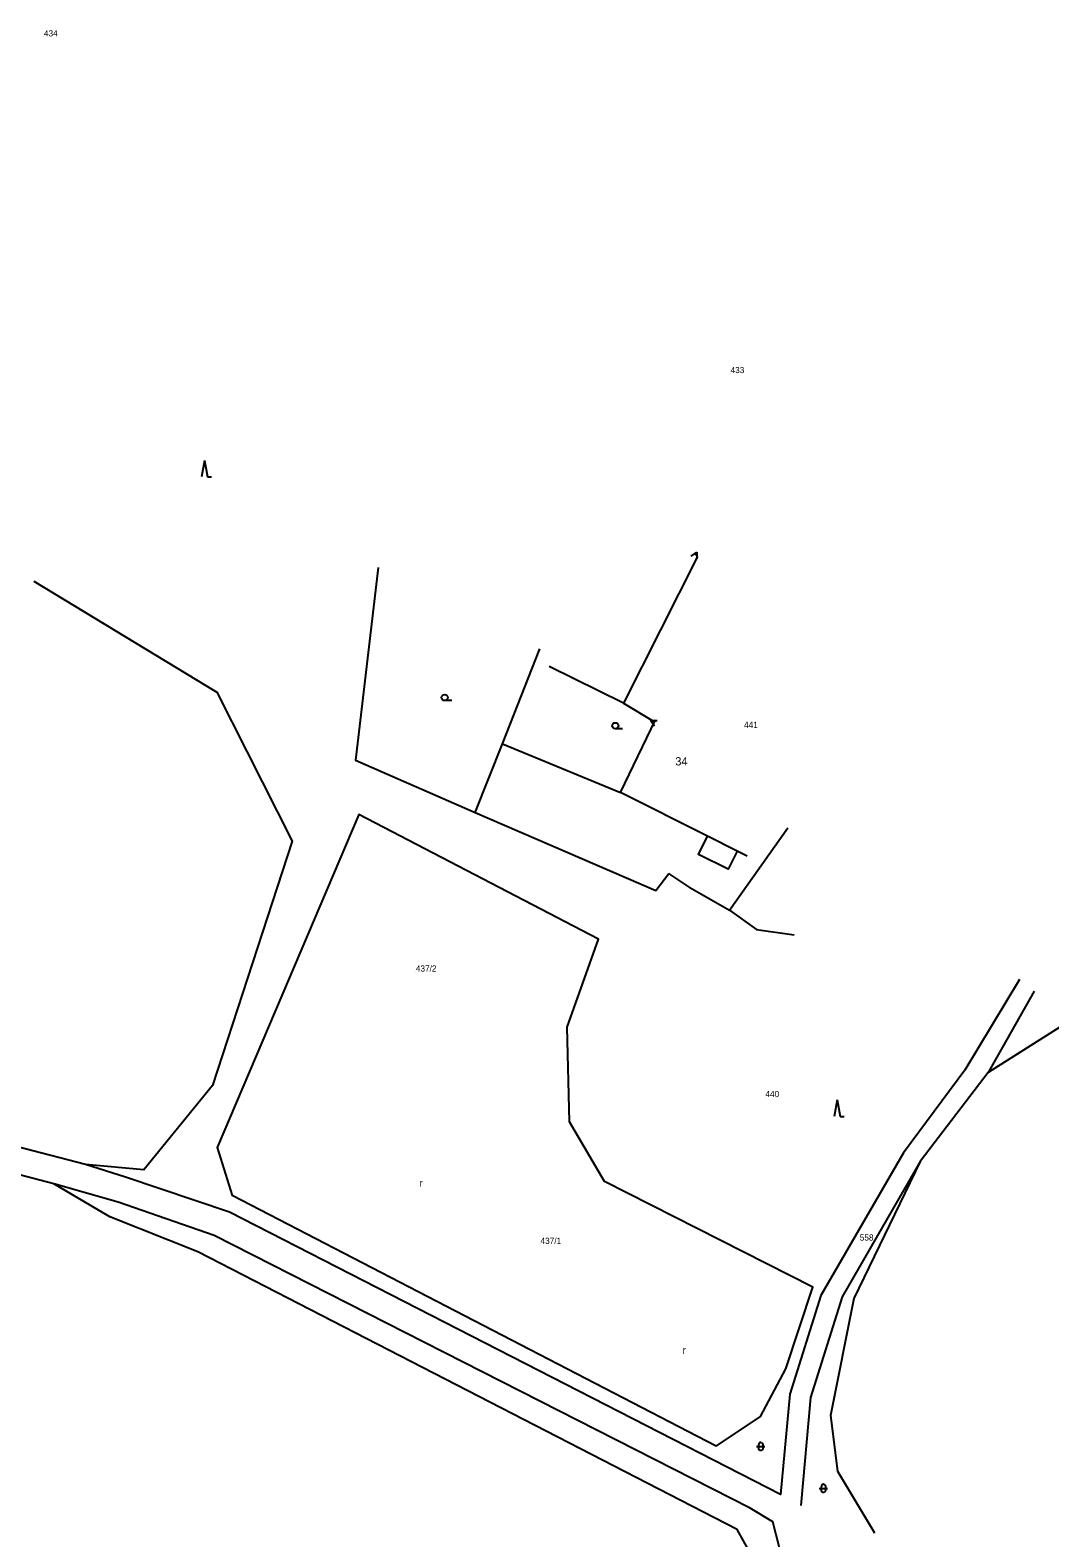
# Model space of a CAD drawing. Extents: x -836739 to -835945, y -1070775 to -1070126.
# Drawn here: x -836135.3 to -836011.5, y -1070527.3 to -1070344.2 of the extents above; entities that cross this region are included whole.
import ezdxf

# ---------------------------------------------------------------- set-up
doc = ezdxf.new("R2010")
doc.units = 0
for name, color, linetype in [('BodPole_mer', 7, 'Continuous'), ('Budovy_hranice', 7, 'Continuous'), ('Doprava_hranice', 7, 'Continuous'), ('OstPloch_hranice', 7, 'Continuous'), ('OstPloch_kody', 7, 'Continuous'), ('PovrZnIS_body', 7, 'Continuous'), ('RuianAdr_popis', 7, 'Continuous'), ('RuianPar_popis', 7, 'Continuous'), ('Stavby_hr_zed', 7, 'Continuous'), ('Stavby_linie', 7, 'Continuous')]:
    doc.layers.add(name, color=color, linetype=linetype)

msp = doc.modelspace()

# ---------------------------------------------------------------- linework, layer by layer
at = {"layer": 'BodPole_mer'}
for p, q in [((-836054.39, -1070407.61), (-836054.39, -1070407.61)), ((-836054.31, -1070408.11), (-836054.31, -1070408.11)), ((-836093.09, -1070409.47), (-836093.09, -1070409.47)), ((-836134.89, -1070411.1), (-836134.89, -1070411.1)), ((-836073.44, -1070419.35), (-836073.44, -1070419.35)), ((-836072.33, -1070421.47), (-836072.33, -1070421.47)), ((-836112.67, -1070424.6), (-836112.67, -1070424.6)), ((-836063.27, -1070425.93), (-836063.27, -1070425.93)), ((-836060, -1070428.04), (-836060, -1070428.04)), ((-836059.53, -1070428.2), (-836059.53, -1070428.2)), ((-836059.4, -1070427.97), (-836059.4, -1070427.97)), ((-836077.99, -1070430.89), (-836077.99, -1070430.89)), ((-836095.81, -1070432.85), (-836095.81, -1070432.85)), ((-836063.66, -1070436.78), (-836063.66, -1070436.78)), ((-836081.31, -1070439.23), (-836081.31, -1070439.23)), ((-836095.44, -1070439.46), (-836095.44, -1070439.46)), ((-836043.33, -1070441.08), (-836043.33, -1070441.08)), ((-836103.5, -1070442.7), (-836103.5, -1070442.7)), ((-836053.08, -1070442.11), (-836053.08, -1070442.11)), ((-836054.2, -1070444.33), (-836054.2, -1070444.33)), ((-836049.48, -1070443.92), (-836049.48, -1070443.92)), ((-836048.27, -1070444.53), (-836048.27, -1070444.53)), ((-836057.77, -1070446.61), (-836057.77, -1070446.61)), ((-836050.58, -1070446.1), (-836050.58, -1070446.1)), ((-836055.24, -1070448.33), (-836055.24, -1070448.33)), ((-836059.36, -1070448.71), (-836059.36, -1070448.71)), ((-836106.5, -1070451.88), (-836106.5, -1070451.88)), ((-836050.41, -1070451.1), (-836050.41, -1070451.1)), ((-836047.12, -1070453.42), (-836047.12, -1070453.42)), ((-836066.32, -1070454.59), (-836066.32, -1070454.59)), ((-836042.58, -1070454.08), (-836042.58, -1070454.08)), ((-836015.21, -1070459.49), (-836015.21, -1070459.49)), ((-836013.42, -1070460.91), (-836013.42, -1070460.91)), ((-836070.12, -1070465.28), (-836070.12, -1070465.28)), ((-836021.84, -1070470.53), (-836021.84, -1070470.53)), ((-836019.02, -1070470.79), (-836019.02, -1070470.79)), ((-836113.2, -1070472.38), (-836113.2, -1070472.38)), ((-836069.83, -1070476.79), (-836069.83, -1070476.79)), ((-836112.64, -1070479.91), (-836112.64, -1070479.91)), ((-836029.29, -1070480.55), (-836029.29, -1070480.55)), ((-836128.61, -1070481.99), (-836128.61, -1070481.99)), ((-836121.53, -1070482.64), (-836121.53, -1070482.64)), ((-836027.28, -1070481.61), (-836027.28, -1070481.61)), ((-836132.47, -1070484.33), (-836132.47, -1070484.33)), ((-836123.74, -1070483.53), (-836123.74, -1070483.53)), ((-836065.58, -1070484.05), (-836065.58, -1070484.05)), ((-836124.66, -1070486.54), (-836124.66, -1070486.54)), ((-836110.8, -1070485.76), (-836110.8, -1070485.76)), ((-836125.66, -1070488.35), (-836125.66, -1070488.35)), ((-836111.13, -1070487.77), (-836111.13, -1070487.77)), ((-836112.97, -1070490.6), (-836112.97, -1070490.6)), ((-836114.97, -1070492.57), (-836114.97, -1070492.57)), ((-836040.28, -1070496.87), (-836040.28, -1070496.87)), ((-836039.31, -1070497.89), (-836039.31, -1070497.89)), ((-836036.73, -1070498.06), (-836036.73, -1070498.06)), ((-836035.31, -1070498.26), (-836035.31, -1070498.26)), ((-836043.57, -1070506.82), (-836043.57, -1070506.82)), ((-836043.1, -1070509.87), (-836043.1, -1070509.87)), ((-836040.6, -1070510.3), (-836040.6, -1070510.3)), ((-836038.16, -1070512.46), (-836038.16, -1070512.46)), ((-836046.67, -1070512.58), (-836046.67, -1070512.58)), ((-836052.04, -1070516.19), (-836052.04, -1070516.19)), ((-836037.32, -1070519.22), (-836037.32, -1070519.22)), ((-836044.22, -1070522.08), (-836044.22, -1070522.08)), ((-836041.77, -1070523.4), (-836041.77, -1070523.4)), ((-836047.92, -1070523.71), (-836047.92, -1070523.71)), ((-836045.14, -1070525.37), (-836045.14, -1070525.37)), ((-836049.49, -1070526.32), (-836049.49, -1070526.32)), ((-836032.81, -1070526.73), (-836032.81, -1070526.73))]:
    msp.add_line(p, q, dxfattribs=at)
at = {"layer": 'Budovy_hranice'}
for points in [[(-836054.31, -1070408.11), (-836063.27, -1070425.93), (-836072.33, -1070421.47)], [(-836048.27, -1070444.53), (-836049.48, -1070443.92), (-836053.08, -1070442.11), (-836063.66, -1070436.78), (-836059.4, -1070427.97)]]:
    msp.add_lwpolyline(points, dxfattribs=at)
at = {"layer": 'Doprava_hranice'}
for points in [[(-836015.21, -1070459.49), (-836021.84, -1070470.53), (-836029.29, -1070480.55), (-836039.31, -1070497.89), (-836043.1, -1070509.87), (-836044.22, -1070522.08), (-836111.13, -1070487.77), (-836123.74, -1070483.53), (-836128.61, -1070481.99), (-836211.76, -1070460.38), (-836245.95, -1070449.75), (-836279.43, -1070438.33), (-836363.94, -1070405.58)], [(-836046.6, -1070544.35), (-836045.64, -1070538.23), (-836044.38, -1070528.39), (-836045.14, -1070525.37), (-836047.92, -1070523.71), (-836112.97, -1070490.6), (-836124.66, -1070486.54), (-836132.47, -1070484.33), (-836212.77, -1070463.28), (-836247.95, -1070452.55), (-836280.73, -1070441.12), (-836361.89, -1070409.63)], [(-836013.42, -1070460.91), (-836019.02, -1070470.79), (-836027.28, -1070481.61), (-836036.73, -1070498.06), (-836040.6, -1070510.3), (-836041.77, -1070523.4)]]:
    msp.add_lwpolyline(points, dxfattribs=at)
at = {"layer": 'OstPloch_hranice'}
msp.add_line((-836052.04, -1070516.19), (-836110.8, -1070485.76), dxfattribs=at)
for points in [[(-836134.89, -1070411.1), (-836112.67, -1070424.6), (-836103.5, -1070442.7), (-836106.5, -1070451.88), (-836113.2, -1070472.38), (-836121.53, -1070482.64), (-836128.61, -1070481.99)], [(-836052.04, -1070516.19), (-836046.67, -1070512.58), (-836043.57, -1070506.82), (-836040.28, -1070496.87), (-836065.58, -1070484.05), (-836069.83, -1070476.79), (-836070.12, -1070465.28), (-836066.32, -1070454.59), (-836095.44, -1070439.46), (-836112.64, -1070479.91), (-836110.8, -1070485.76)], [(-835945.4, -1070467.08), (-835964.25, -1070468.37), (-835992.51, -1070462.29), (-836006.79, -1070463.08), (-836019.02, -1070470.79)], [(-836027.28, -1070481.61), (-836035.31, -1070498.26), (-836038.16, -1070512.46), (-836037.32, -1070519.22), (-836032.81, -1070526.73)], [(-836047.55, -1070546.79), (-836046.42, -1070531.83), (-836049.49, -1070526.32), (-836114.97, -1070492.57), (-836125.66, -1070488.35), (-836132.47, -1070484.33)]]:
    msp.add_lwpolyline(points, dxfattribs=at)
at = {"layer": 'OstPloch_kody'}
for p, q in [((-836114.17, -1070396.46), (-836114.54, -1070398.46)), ((-836114.17, -1070396.46), (-836113.8, -1070398.46)), ((-836113.8, -1070398.46), (-836113.3, -1070398.46)), ((-836084.12, -1070425.63), (-836085, -1070425.63)), ((-836063.4, -1070429.06), (-836064.27, -1070429.06)), ((-836037.35, -1070474.14), (-836037.72, -1070476.14)), ((-836037.35, -1070474.14), (-836036.98, -1070476.14)), ((-836036.98, -1070476.14), (-836036.48, -1070476.14)), ((-836047.12, -1070516.24), (-836046.12, -1070516.24)), ((-836046.87, -1070516.49), (-836046.87, -1070515.99)), ((-836046.37, -1070515.99), (-836046.37, -1070516.49)), ((-836039.51, -1070521.33), (-836038.51, -1070521.33)), ((-836039.26, -1070521.58), (-836039.26, -1070521.08)), ((-836038.76, -1070521.08), (-836038.76, -1070521.58))]:
    msp.add_line(p, q, dxfattribs=at)
for points in [[(-836046.62, -1070515.74), (-836046.67, -1070515.74), (-836046.71, -1070515.76), (-836046.76, -1070515.78), (-836046.8, -1070515.81), (-836046.83, -1070515.85), (-836046.85, -1070515.9), (-836046.87, -1070515.94), (-836046.87, -1070515.99)], [(-836046.62, -1070515.74), (-836046.57, -1070515.74), (-836046.53, -1070515.76), (-836046.48, -1070515.78), (-836046.44, -1070515.81), (-836046.41, -1070515.85), (-836046.39, -1070515.9), (-836046.37, -1070515.94), (-836046.37, -1070515.99)], [(-836046.62, -1070516.74), (-836046.67, -1070516.74), (-836046.71, -1070516.72), (-836046.76, -1070516.7), (-836046.8, -1070516.67), (-836046.83, -1070516.63), (-836046.85, -1070516.58), (-836046.87, -1070516.54), (-836046.87, -1070516.49)], [(-836046.37, -1070516.49), (-836046.37, -1070516.54), (-836046.39, -1070516.58), (-836046.41, -1070516.63), (-836046.44, -1070516.67), (-836046.48, -1070516.7), (-836046.53, -1070516.72), (-836046.57, -1070516.74), (-836046.62, -1070516.74)], [(-836039.01, -1070520.83), (-836039.06, -1070520.83), (-836039.1, -1070520.85), (-836039.15, -1070520.87), (-836039.19, -1070520.9), (-836039.22, -1070520.94), (-836039.24, -1070520.99), (-836039.26, -1070521.03), (-836039.26, -1070521.08)], [(-836039.01, -1070521.83), (-836039.06, -1070521.83), (-836039.1, -1070521.81), (-836039.15, -1070521.79), (-836039.19, -1070521.76), (-836039.22, -1070521.72), (-836039.24, -1070521.67), (-836039.26, -1070521.63), (-836039.26, -1070521.58)], [(-836039.01, -1070520.83), (-836038.96, -1070520.83), (-836038.92, -1070520.85), (-836038.87, -1070520.87), (-836038.83, -1070520.9), (-836038.8, -1070520.94), (-836038.78, -1070520.99), (-836038.76, -1070521.03), (-836038.76, -1070521.08)], [(-836038.76, -1070521.58), (-836038.76, -1070521.63), (-836038.78, -1070521.67), (-836038.8, -1070521.72), (-836038.83, -1070521.76), (-836038.87, -1070521.79), (-836038.92, -1070521.81), (-836038.96, -1070521.83), (-836039.01, -1070521.83)]]:
    msp.add_lwpolyline(points, dxfattribs=at)
for centre in [(-836085, -1070425.25), (-836064.27, -1070428.68)]:
    msp.add_ellipse(centre, major_axis=(0.375, 0), ratio=0.999999, dxfattribs=at)
at = {"layer": 'PovrZnIS_body'}
for p, q in [((-836055.06, -1070408.07), (-836054.39, -1070407.61)), ((-836054.39, -1070407.97), (-836054.69, -1070407.82)), ((-836054.6, -1070407.81), (-836054.44, -1070407.71)), ((-836054.6, -1070407.81), (-836054.43, -1070407.9)), ((-836054.47, -1070407.77), (-836054.53, -1070407.82)), ((-836054.53, -1070407.82), (-836054.46, -1070407.85)), ((-836054.46, -1070407.85), (-836054.47, -1070407.77)), ((-836054.44, -1070407.71), (-836054.42, -1070407.91)), ((-836054.39, -1070407.61), (-836054.39, -1070408.42)), ((-836059.54, -1070428.71), (-836060, -1070428.04)), ((-836060, -1070428.04), (-836059.19, -1070428.04)), ((-836059.9, -1070428.09), (-836059.7, -1070428.07)), ((-836059.8, -1070428.25), (-836059.9, -1070428.09)), ((-836059.76, -1070428.11), (-836059.84, -1070428.12)), ((-836059.84, -1070428.12), (-836059.79, -1070428.18)), ((-836059.8, -1070428.25), (-836059.71, -1070428.08)), ((-836059.64, -1070428.04), (-836059.79, -1070428.34)), ((-836059.79, -1070428.18), (-836059.76, -1070428.11))]:
    msp.add_line(p, q, dxfattribs=at)
at = {"layer": 'RuianAdr_popis'}
msp.add_line((-836057, -1070433.5), (-836057, -1070433.5), dxfattribs=at)
at = {"layer": 'RuianPar_popis'}
for p, q in [((-836133.66, -1070344.94), (-836133.66, -1070344.94)), ((-836050.29, -1070385.84), (-836050.29, -1070385.84)), ((-836048.65, -1070428.95), (-836048.65, -1070428.95)), ((-836088.5, -1070458.54), (-836088.5, -1070458.54)), ((-836046.06, -1070473.79), (-836046.06, -1070473.79)), ((-836073.36, -1070491.62), (-836073.36, -1070491.62)), ((-836034.6, -1070491.22), (-836034.6, -1070491.22))]:
    msp.add_line(p, q, dxfattribs=at)
at = {"layer": 'Stavby_hr_zed'}
msp.add_lwpolyline([(-836049.48, -1070443.92), (-836050.58, -1070446.1), (-836054.2, -1070444.33), (-836053.08, -1070442.11)], dxfattribs=at)
at = {"layer": 'Stavby_linie'}
for p, q in [((-836063.27, -1070425.93), (-836059.53, -1070428.2)), ((-836077.99, -1070430.89), (-836063.66, -1070436.78)), ((-836055.24, -1070448.33), (-836057.77, -1070446.61))]:
    msp.add_line(p, q, dxfattribs=at)
for points in [[(-836093.09, -1070409.47), (-836095.81, -1070432.85), (-836081.31, -1070439.23), (-836059.36, -1070448.71), (-836057.77, -1070446.61)], [(-836081.31, -1070439.23), (-836077.99, -1070430.89), (-836073.44, -1070419.35)], [(-836055.24, -1070448.33), (-836050.41, -1070451.1), (-836043.33, -1070441.08)], [(-836050.41, -1070451.1), (-836047.12, -1070453.42), (-836042.58, -1070454.08)]]:
    msp.add_lwpolyline(points, dxfattribs=at)

# ---------------------------------------------------------------- texts
at = {"layer": 'OstPloch_kody'}
for p in [(-836088.05, -1070484.67), (-836056.12, -1070504.98)]:
    msp.add_text('r', height=0.9, dxfattribs=at).set_placement(p)
at = {"layer": 'RuianAdr_popis'}
msp.add_text('34', height=1, dxfattribs=at).set_placement((-836057, -1070433.5))
at = {"layer": 'RuianPar_popis'}
for s, p in [('434', (-836133.66, -1070344.94)), ('433', (-836050.29, -1070385.84)), ('441', (-836048.65, -1070428.95)), ('437/2', (-836088.5, -1070458.54)), ('440', (-836046.06, -1070473.79)), ('558', (-836034.6, -1070491.22)), ('437/1', (-836073.36, -1070491.62))]:
    msp.add_text(s, height=0.75, dxfattribs=at).set_placement(p)

doc.saveas('drawing.dxf')
